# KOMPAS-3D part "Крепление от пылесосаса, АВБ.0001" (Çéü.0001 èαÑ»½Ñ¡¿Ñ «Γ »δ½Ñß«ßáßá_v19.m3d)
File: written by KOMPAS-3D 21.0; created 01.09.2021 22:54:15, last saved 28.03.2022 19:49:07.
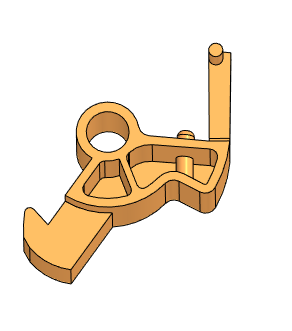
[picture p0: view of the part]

Document properties: Полное имя файла: D:\3D_print\011Крепление пылесоса Xiaomi\АВБ.0001 Крепление от пылесосаса_v19.m3d

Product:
- Part/product: Крепление от пылесосаса  | designation АВБ.0001
    Масса: 0.026936

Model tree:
1. Эскиз:1
2. Эскиз:2
3. Элемент выдавливания:1
     Расстояние 1 = 12
4. Эскиз:3  (with: Элемент выдавливания:1)
5. Элемент выдавливания:2
     Расстояние 1 = 3.5
6. Эскиз:4  (with: Элемент выдавливания:1)
7. Элемент выдавливания:3
     Расстояние 2 = 10
8. Эскиз:5  (with: Элемент выдавливания:3)
9. Элемент выдавливания:4  (with: Элемент выдавливания:1)
     Расстояние 1 = 3; Расстояние 2 = 9
10. Эскиз:6  (with: Элемент выдавливания:1)
11. Элемент выдавливания:5
     Расстояние 2 = 3.5
12. Скругление:1
     Радиус = 1
13. Эскиз:7  (with: Элемент выдавливания:1)
14. Элемент выдавливания:6
     Расстояние 2 = 10
15. Элемент выдавливания:7  (with: Элемент выдавливания:2, Элемент выдавливания:6)
     Расстояние 1 = -6.4987
16. Эскиз:8  (with: Элемент выдавливания:1)
17. Элемент выдавливания:8  (with: Элемент выдавливания:1)
     Толщина стенки 1 = 1.2; Расстояние 1 = -12
18. Скругление:2
     Радиус = 1
19. Скругление:3
     Радиус = 2

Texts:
  АВБ.0001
